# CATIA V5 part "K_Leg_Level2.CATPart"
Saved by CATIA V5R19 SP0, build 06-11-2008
Part number: Leg_Level2
Bounding box of the stored display mesh (mm): x -22.213 to 22.213, y 52.055 to 69.993, z -636.695 to 38.305
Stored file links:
  G:\Khaled_CFAO_2011\SIL\SIL_GR2\ctanaphiko\Khaled\CAD_ThinkMOTION\K_Leg_Level2.CATPart
  G:\Khaled_CFAO_2011\SIL\SIL_GR2\ctanaphiko\CATIA\Conception_Tripod.CATProduct
  G:\Khaled_CFAO_2011\SIL\SIL_GR2\ctanaphiko\CATIA\Squelette.CATPart
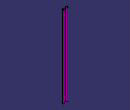
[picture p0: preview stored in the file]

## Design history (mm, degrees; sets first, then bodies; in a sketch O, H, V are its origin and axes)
External parameters (linked from other documents)
  External.Dia_Leg_Step2 = 18 mm
  External.Thick_Leg_Step2 = 1.8 mm
AxisSystem1: origin (0, 0, 0), X (1, 0, 0), Y (0, 1, 0), Z (0, 0, 1)
Set1
  Plane1 "Plan_S1": linked copy from another document
  Point1: linked copy from another document
  Point2: linked copy from another document
  Line1: linked copy from another document
Body1 (main body)
  Sketch1 on Plane1, origin (0, 0, 38.3053), H (1, 0, 0), V (0, 1, 0)
    circle A1 centre (-13.2127, 61.024) radius 9
    point P1 (-13.2127, 61.024)
    reference projected point E1 (-13.2127, 61.024) from Point1
    circle A2 centre (13.2127, 61.024) radius 9
    point P2 (13.2127, 61.024)
    reference projected point E2 (13.2127, 61.024) from Point2
    radius A1 = 9 {= External.Dia_Leg_Step2 /2}
    radius A2 = 9 {= External.Dia_Leg_Step2 /2}
    coincidence: P1 E1, P2 E2
  Rib1: profile Sketch1, centre curve Line1, thin wall 1.8 {= External.Thick_Leg_Step2}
